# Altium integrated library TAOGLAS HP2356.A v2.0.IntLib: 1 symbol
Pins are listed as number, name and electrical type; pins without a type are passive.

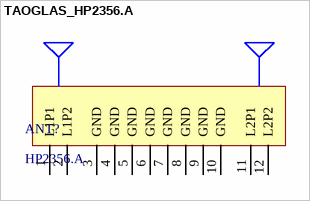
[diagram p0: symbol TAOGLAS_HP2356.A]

## TAOGLAS_HP2356.A
designator ANT?, comment HP2356.A
Inception Series Low Profile High Precision GNSS L1/L2 Passive Patch Antenna; ComponentLibStatus: Created; MFG: Taoglas; Temp_High: +85C; Temp_Low: -40C
footprint TAOGLAS_HP2356.A (Inception Series Low Profile High Precision GNSS L1/L2 Passive Patch Antenna)
pins: 1 L1P1, 2 L1P2, 3 GND, 4 GND, 5 GND, 6 GND, 7 GND, 8 GND, 9 GND, 10 GND, 11 L2P1, 12 L2P2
